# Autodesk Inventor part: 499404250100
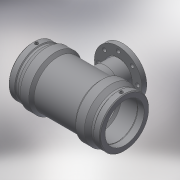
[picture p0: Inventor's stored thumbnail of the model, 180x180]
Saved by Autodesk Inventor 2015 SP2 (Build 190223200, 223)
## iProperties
Created: 2017-06
Part Number: 499404250100
Material: Generic
Description: PLASSON FLANGED TEE 250x100x250
Document SubType Name: Modeling
Designer: KIM
Mass: 57.3761 g
Surface Area: 241.06 cm^2
Volume: 57.3761 cm^3
Density: 1 g/cm^3
Appearance: Default
Author: KIM
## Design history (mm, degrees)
derived "499404.ipt"
feature "Solid1::499404.ipt"
tag "TaggingFeature1"
body "Solid1"
other parameters: "d13" = 538, "d14" = 17.6296, "d17" = 225, "d19" = 3.52592, "d20" = 168 deg, "d22" = 303.18, "d23" = 326, "d24" = 294.0846, "d25" = 135 deg, "d26" = 376.6, "d27" = 135 deg, "d29" = 152, "d35" = 15, "d39" = 5 deg, "d45" = 4, "d46" = 14, "d47" = 0, "d48" = -275, "d55" = 293.4, "d56" = 326, "d57" = 188.3, "d58" = 135 deg, "d59" = 129, "d60" = 129, "d61" = 135 deg, "d62" = 275, "d72" = 244.79, "d73" = 122.395, "d74" = -275, "d84" = 275, "d87" = 158, "d90" = 125, "d91" = 15 deg, "d93" = 22, "d95" = 4.74, "d97" = 18, "d100" = 0, "d102" = 360 deg, "d105" = 0, "d107" = 0, "d108" = 3, "d109" = 0, "d110" = 38.7, "d111" = 12.9, "L_" = 538, "L_1" = 129, "D_" = 326, "A_" = 152, "d_2" = 12, "H_" = 275, "t_" = 22, "d_1" = 158, "s_" = 18
